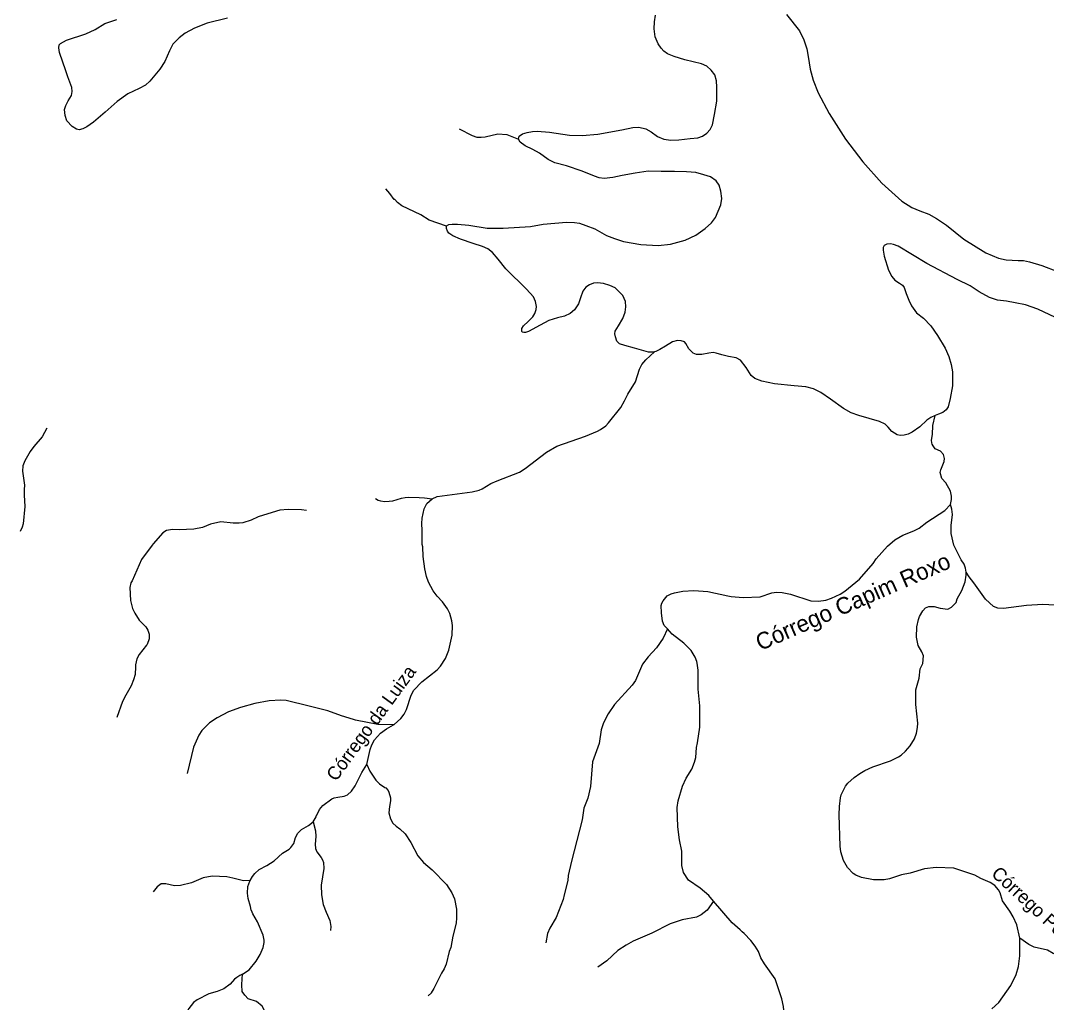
# Model space of a CAD drawing. Extents: x 396 to 422.2, y 7649.8 to 7677.6.
# Drawn here: x 409.11 to 415.26, y 7662.43 to 7668.32 of the extents above; entities that cross this region are included whole.
import ezdxf
from ezdxf.enums import TextEntityAlignment as Align

# ---------------------------------------------------------------- set-up
doc = ezdxf.new("R2010")
doc.units = 0
doc.header["$LTSCALE"] = 0.032
doc.layers.add('2', color=7, linetype='Continuous', lineweight=25)
doc.layers.add('7', color=7, linetype='Continuous', lineweight=25)
doc.layers.add('61', color=7, linetype='Continuous')

msp = doc.modelspace()

# ---------------------------------------------------------------- linework, layer by layer
at = {"layer": '2'}
for points in [[(409.9784, 7668.0764), (409.947, 7668.0312), (409.888, 7667.9584), (409.8614, 7667.9348), (409.8241, 7667.9151), (409.7552, 7667.8817), (409.6913, 7667.8365), (409.6195, 7667.7716), (409.5497, 7667.7136), (409.5094, 7667.685), (409.4858, 7667.6723), (409.4652, 7667.6664), (409.4484, 7667.6703), (409.4219, 7667.687), (409.3914, 7667.7204), (409.3796, 7667.7529), (409.3767, 7667.7883), (409.3835, 7667.8119), (409.3993, 7667.8404), (409.418, 7667.8719), (409.4219, 7667.8955), (409.4199, 7667.9201), (409.3973, 7667.985), (409.3853, 7668.0195), (409.3472, 7668.1295), (409.3422, 7668.159), (409.3442, 7668.1757), (409.3521, 7668.1846), (409.3885, 7668.2042), (409.5035, 7668.2416), (409.5596, 7668.2681), (409.6186, 7668.3035), (409.6893, 7668.3281)], [(410.3541, 7668.336), (410.2321, 7668.3065), (410.1564, 7668.276)], [(412.0974, 7667.6113), (412.1024, 7667.628), (412.121, 7667.6418), (412.1486, 7667.6516), (412.181, 7667.6565), (412.2095, 7667.6585), (412.2843, 7667.6526), (412.4023, 7667.6349), (412.4799, 7667.6319), (412.5724, 7667.6398), (412.7159, 7667.6664), (412.7828, 7667.6801), (412.8192, 7667.6831), (412.8605, 7667.6723), (412.8929, 7667.6546), (412.9313, 7667.627), (412.9696, 7667.6113), (413.0109, 7667.6054), (413.0581, 7667.6064), (413.126, 7667.6142), (413.1732, 7667.6192), (413.2007, 7667.629), (413.2273, 7667.6457), (413.2469, 7667.6683), (413.2597, 7667.6968), (413.2715, 7667.7578), (413.2862, 7667.8384), (413.2872, 7667.923), (413.2833, 7667.9614), (413.2735, 7667.9958), (413.2518, 7668.0253), (413.2263, 7668.0479), (413.1938, 7668.0626), (413.0935, 7668.0862), (413.0296, 7668.1059), (412.9903, 7668.1226), (412.9677, 7668.1383), (412.9519, 7668.156), (412.9352, 7668.1826), (412.9175, 7668.2249), (412.9106, 7668.2721), (412.9126, 7668.3134), (412.9185, 7668.3547)], [(413.7032, 7668.3576), (413.7808, 7668.2593), (413.8084, 7668.2072), (413.8251, 7668.1521), (413.8339, 7668.1069), (413.8448, 7668.0312), (413.8644, 7667.9653), (413.8939, 7667.8886), (413.9598, 7667.7637), (414.0572, 7667.6113), (414.1604, 7667.4746), (414.2745, 7667.3468), (414.3954, 7667.2396), (414.4554, 7667.2003), (414.5026, 7667.1816), (414.5577, 7667.1619), (414.6029, 7667.1354), (414.6638, 7667.0951), (414.7661, 7667.0105), (414.8989, 7666.9289), (414.9746, 7666.8964), (415.0208, 7666.8876), (415.0916, 7666.8827), (415.125, 7666.8827), (415.1604, 7666.8758), (415.2342, 7666.8532), (415.3286, 7666.8178)], [(410.1564, 7668.276), (410.1004, 7668.2465), (410.064, 7668.219), (410.0266, 7668.1806), (410.006, 7668.1413), (409.9784, 7668.0764)], [(411.6655, 7667.0882), (411.6658, 7667.0902), (411.6805, 7667.099), (411.6992, 7667.101), (411.7317, 7667.102), (411.8005, 7667.0941), (411.9096, 7667.0774), (412.005, 7667.0764), (412.1702, 7667.0872), (412.2459, 7667.101), (412.3846, 7667.1128), (412.4337, 7667.1108), (412.4622, 7667.1069), (412.5006, 7667.0931), (412.5557, 7667.0725), (412.6255, 7667.0321), (412.6727, 7667.0144), (412.7277, 7666.9977), (412.83, 7666.98), (412.9352, 7666.9731), (413.009, 7666.981), (413.0965, 7667.0056), (413.1614, 7667.0351), (413.2164, 7667.0744), (413.2538, 7667.1088), (413.2774, 7667.1413), (413.3108, 7667.217), (413.3157, 7667.2544), (413.3108, 7667.2986), (413.301, 7667.334), (413.2823, 7667.3606), (413.2489, 7667.3842), (413.2086, 7667.3969), (413.1604, 7667.4107), (413.1043, 7667.4146), (413.0335, 7667.4166), (412.9529, 7667.4176), (412.8742, 7667.4186), (412.7966, 7667.4078), (412.7179, 7667.392), (412.6638, 7667.3812), (412.6107, 7667.3753), (412.5802, 7667.3783), (412.5527, 7667.3881), (412.479, 7667.4186), (412.3855, 7667.45), (412.3157, 7667.4687), (412.2754, 7667.4884), (412.2233, 7667.5267), (412.183, 7667.5494), (412.1368, 7667.571), (412.1083, 7667.5936), (412.0974, 7667.6113)], [(412.9118, 7666.3352), (412.9047, 7666.333), (412.8772, 7666.333), (412.7936, 7666.3576), (412.7356, 7666.3733), (412.7022, 7666.3832), (412.6874, 7666.3999), (412.6786, 7666.4245), (412.6746, 7666.4441), (412.6776, 7666.4599), (412.6963, 7666.4913), (412.7238, 7666.5346), (412.7366, 7666.5729), (412.7415, 7666.6054), (412.7395, 7666.6369), (412.7238, 7666.6723), (412.6766, 7666.7185), (412.6442, 7666.7342), (412.6068, 7666.745), (412.5714, 7666.7489), (412.5468, 7666.747), (412.5222, 7666.7381), (412.5016, 7666.7224), (412.4839, 7666.6988), (412.4691, 7666.6595), (412.4563, 7666.6241), (412.4327, 7666.5867), (412.4082, 7666.5651), (412.3737, 7666.5493), (412.3305, 7666.5395), (412.2784, 7666.5238), (412.2282, 7666.4962), (412.1584, 7666.4569), (412.1397, 7666.451), (412.1299, 7666.451), (412.1191, 7666.453), (412.1171, 7666.4589), (412.1171, 7666.4756), (412.1279, 7666.4923), (412.1545, 7666.5169), (412.183, 7666.5454), (412.1958, 7666.5651), (412.2036, 7666.5887), (412.2046, 7666.6064), (412.1987, 7666.6378), (412.1869, 7666.6644), (412.1456, 7666.7106), (412.0217, 7666.8335), (411.9755, 7666.8915), (411.9421, 7666.9309), (411.9145, 7666.9525), (411.8811, 7666.9663), (411.8251, 7666.9859), (411.7494, 7667.0115), (411.7041, 7667.0312), (411.6805, 7667.0469), (411.6727, 7667.0587), (411.6658, 7667.0744), (411.6655, 7667.0882)], [(415.3168, 7666.5415), (415.2096, 7666.5906), (415.1358, 7666.6182), (415.0749, 7666.63), (415.0218, 7666.6388), (414.9687, 7666.6457), (414.9205, 7666.6614), (414.8585, 7666.6949), (414.8054, 7666.7312), (414.7268, 7666.7696), (414.5459, 7666.866), (414.3728, 7666.9692), (414.3453, 7666.98), (414.3276, 7666.983), (414.3049, 7666.982), (414.2892, 7666.9722), (414.2833, 7666.9604), (414.2833, 7666.9446), (414.2902, 7666.9092), (414.3148, 7666.8256), (414.3344, 7666.7873), (414.3531, 7666.7647), (414.3816, 7666.748), (414.3984, 7666.7362), (414.4092, 7666.7204), (414.421, 7666.685), (414.4367, 7666.6447), (414.4534, 7666.6123), (414.4839, 7666.569), (414.5252, 7666.5366), (414.5695, 7666.4913), (414.6088, 7666.4333), (414.655, 7666.3576), (414.6776, 7666.3074), (414.6914, 7666.2593), (414.6992, 7666.216), (414.6983, 7666.1314), (414.6855, 7666.0557), (414.6727, 7666.0066), (414.6609, 7665.9879), (414.6412, 7665.9712), (414.6157, 7665.9613), (414.5946, 7665.9538)], [(414.5946, 7665.9538), (414.5695, 7665.9417), (414.5459, 7665.9259), (414.5026, 7665.8866), (414.4574, 7665.8532), (414.4328, 7665.8423), (414.4082, 7665.8364), (414.3846, 7665.8345), (414.3679, 7665.8384), (414.3354, 7665.8571), (414.3138, 7665.8846), (414.2961, 7665.9013), (414.2607, 7665.9171), (414.1368, 7665.9535), (414.0916, 7665.9692), (414.0454, 7665.9948), (413.9677, 7666.0508), (413.9097, 7666.0911), (413.8654, 7666.1128), (413.8192, 7666.1265), (413.7494, 7666.1314), (413.6314, 7666.1442), (413.5567, 7666.159), (413.5134, 7666.1757), (413.4918, 7666.1934), (413.4623, 7666.2425), (413.4278, 7666.2858), (413.4023, 7666.2996), (413.357, 7666.3074), (413.3167, 7666.3173), (413.2823, 7666.3271), (413.2636, 7666.331), (413.2391, 7666.3271), (413.1968, 7666.3192), (413.1653, 7666.3192), (413.1437, 7666.3271), (413.1191, 7666.3537), (413.1014, 7666.3851), (413.0916, 7666.395), (413.0729, 7666.4009), (413.0512, 7666.4028), (413.0198, 7666.395), (412.9785, 7666.3704), (412.945, 7666.3497), (412.9205, 7666.3379), (412.9118, 7666.3352)]]:
    msp.add_lwpolyline(points, dxfattribs=at)
at = {"layer": '7'}
msp.add_line((413.0195, 7664.6423), (412.9904, 7664.6743), dxfattribs=at)
for points in [[(411.7419, 7667.6727), (411.8192, 7667.6323), (411.8471, 7667.6235), (411.8729, 7667.6218), (411.8985, 7667.6242), (411.9743, 7667.6424), (412.028, 7667.6389), (412.0974, 7667.6113)], [(411.6655, 7667.0882), (411.5626, 7667.1246), (411.5119, 7667.1572), (411.3979, 7667.2118), (411.3724, 7667.2301), (411.3564, 7667.2484), (411.3531, 7667.2488), (411.3271, 7667.2851), (411.3028, 7667.3125)], [(411.5804, 7665.4545), (411.6101, 7665.4685), (411.8195, 7665.4965), (411.861, 7665.5066), (411.8795, 7665.5142), (411.9323, 7665.5461), (411.9694, 7665.563), (412.1029, 7665.6139), (412.1373, 7665.6353), (412.2663, 7665.7345), (412.3276, 7665.7697), (412.4982, 7665.829), (412.5708, 7665.859), (412.5898, 7665.8694), (412.6207, 7665.8926), (412.6369, 7665.9095), (412.71, 7666.0014), (412.7319, 7666.042), (412.753, 7666.0811), (412.7979, 7666.1565), (412.8229, 7666.2321), (412.8362, 7666.2593), (412.8616, 7666.2882), (412.9118, 7666.3352)], [(414.6859, 7665.4207), (414.6925, 7665.4508), (414.6929, 7665.4697), (414.6858, 7665.5009), (414.6584, 7665.5494), (414.634, 7665.5755), (414.6255, 7665.611), (414.628, 7665.6271), (414.6483, 7665.6787), (414.6506, 7665.6958), (414.6449, 7665.7198), (414.6267, 7665.7397), (414.5943, 7665.7547), (414.5819, 7665.7712), (414.5776, 7665.7819), (414.5747, 7665.7891), (414.5726, 7665.8063), (414.578, 7665.8407), (414.5804, 7665.8933), (414.5946, 7665.9538)], [(409.27, 7665.8786), (409.2426, 7665.8256), (409.1917, 7665.7684), (409.1706, 7665.7383), (409.1631, 7665.7248), (409.1391, 7665.6815), (409.1276, 7665.6515), (409.1249, 7665.6209), (409.1359, 7665.537), (409.1352, 7665.5103), (409.1343, 7665.476), (409.1383, 7665.4073), (409.1279, 7665.3051), (409.1232, 7665.2844), (409.1113, 7665.2581)], [(411.2402, 7665.4567), (411.2564, 7665.4468), (411.2699, 7665.4414), (411.2969, 7665.4382), (411.3222, 7665.4392), (411.3447, 7665.4423), (411.396, 7665.4585), (411.4181, 7665.463), (411.441, 7665.4648), (411.5027, 7665.463), (411.5349, 7665.4595), (411.5804, 7665.4545)], [(411.5205, 7665.1804), (411.5205, 7665.2637), (411.5172, 7665.3067), (411.5205, 7665.339), (411.5329, 7665.3947), (411.5487, 7665.4255), (411.5804, 7665.4545)], [(412.9904, 7664.6743), (412.9713, 7664.6953), (412.9597, 7664.7205), (412.9538, 7664.7702), (412.952, 7664.8151), (412.956, 7664.8289), (412.9643, 7664.8434), (412.9892, 7664.873), (413.0131, 7664.8847), (413.0333, 7664.891), (413.0827, 7664.8999), (413.1477, 7664.9039), (413.2332, 7664.8976), (413.352, 7664.8718), (413.3714, 7664.8676), (413.4432, 7664.8625), (413.5458, 7664.8656), (413.6153, 7664.89), (413.6436, 7664.8935), (413.6773, 7664.8927), (413.7276, 7664.8825), (413.8504, 7664.8434), (413.8957, 7664.8409), (413.9389, 7664.8474), (413.9732, 7664.8591), (414.0254, 7664.8832), (414.0544, 7664.9001), (414.141, 7664.9725), (414.223, 7665.0656), (414.2422, 7665.0936), (414.3099, 7665.1693), (414.3538, 7665.2085), (414.4005, 7665.2367), (414.4677, 7665.2627), (414.4996, 7665.2786), (414.5442, 7665.3134), (414.6519, 7665.3838), (414.6859, 7665.4207)], [(414.7816, 7665.0153), (414.7772, 7665.0374), (414.7678, 7665.0621), (414.7501, 7665.0885), (414.7058, 7665.1756), (414.6898, 7665.2457), (414.6903, 7665.295), (414.6994, 7665.3597), (414.6946, 7665.3925), (414.6859, 7665.4207)], [(410.8274, 7665.3833), (410.7961, 7665.3875), (410.7166, 7665.3893), (410.668, 7665.3858), (410.543, 7665.348), (410.5373, 7665.3463), (410.4956, 7665.3261), (410.4459, 7665.3104), (410.4238, 7665.3075), (410.388, 7665.3082), (410.3139, 7665.3154), (410.2515, 7665.3028), (410.2034, 7665.2828), (410.1526, 7665.2724), (410.0645, 7665.2677), (410.024, 7665.2699), (409.9882, 7665.2645), (409.9659, 7665.2506), (409.9083, 7665.1846), (409.9017, 7665.177), (409.8389, 7665.0904), (409.7821, 7664.9625), (409.7739, 7664.9507), (409.7676, 7664.9216), (409.7724, 7664.8454), (409.7849, 7664.797), (409.7977, 7664.7677), (409.8243, 7664.726), (409.863, 7664.6873), (409.8767, 7664.6658), (409.884, 7664.6428), (409.884, 7664.614), (409.8714, 7664.5812), (409.8675, 7664.5762), (409.8244, 7664.5206), (409.8108, 7664.4951), (409.8011, 7664.4585), (409.8026, 7664.4342), (409.8006, 7664.4137), (409.7994, 7664.4007), (409.7903, 7664.3683), (409.776, 7664.3331), (409.7432, 7664.277), (409.725, 7664.239), (409.6895, 7664.1432)], [(411.3483, 7664.0999), (411.3518, 7664.1019), (411.3927, 7664.1377), (411.4122, 7664.1633), (411.4268, 7664.1911), (411.4548, 7664.2772), (411.4699, 7664.3072), (411.5181, 7664.3568), (411.6104, 7664.4293), (411.6299, 7664.4512), (411.661, 7664.4967), (411.679, 7664.5464), (411.6991, 7664.6368), (411.7023, 7664.6946), (411.7023, 7664.6949), (411.6983, 7664.7229), (411.6856, 7664.7657), (411.6717, 7664.7954), (411.643, 7664.8372), (411.6096, 7664.8707), (411.586, 7664.9028), (411.5573, 7664.9539), (411.5457, 7664.9875), (411.5365, 7665.0336), (411.5269, 7665.1086), (411.5236, 7665.1663), (411.5205, 7665.1804)], [(415.1022, 7662.819), (415.0842, 7662.9006), (415.0618, 7662.9484), (415.0428, 7662.9815), (414.9977, 7663.0439), (414.9848, 7663.0912), (414.975, 7663.1091), (414.9521, 7663.136), (414.9245, 7663.1533), (414.868, 7663.1767), (414.8324, 7663.1973), (414.7064, 7663.2396), (414.6012, 7663.2443), (414.5311, 7663.2346), (414.4445, 7663.2101), (414.3938, 7663.1988), (414.3221, 7663.1759), (414.2891, 7663.1693), (414.2244, 7663.1701), (414.1538, 7663.1838), (414.1201, 7663.1975), (414.1029, 7663.2082), (414.0698, 7663.2438), (414.0451, 7663.285), (414.0295, 7663.3365), (414.0254, 7663.3719), (414.019, 7663.5585), (414.0214, 7663.6093), (414.0276, 7663.6608), (414.0323, 7663.6791), (414.058, 7663.7321), (414.072, 7663.7495), (414.1096, 7663.7831), (414.1432, 7663.8079), (414.1729, 7663.8257), (414.2221, 7663.8471), (414.3273, 7663.8838), (414.3742, 7663.9067), (414.3911, 7663.918), (414.4176, 7663.9419), (414.4459, 7663.9738), (414.4703, 7664.0144), (414.4829, 7664.0491), (414.4896, 7664.0821), (414.4912, 7664.1096), (414.48, 7664.2202), (414.4791, 7664.3079), (414.4983, 7664.3785), (414.5048, 7664.434), (414.5207, 7664.4665), (414.5242, 7664.5122), (414.5152, 7664.536), (414.4939, 7664.5751), (414.4831, 7664.6244), (414.4857, 7664.6856), (414.4944, 7664.7297), (414.5006, 7664.7482), (414.5204, 7664.7818), (414.5376, 7664.8002), (414.5566, 7664.809), (414.5892, 7664.809), (414.6251, 7664.7977), (414.6704, 7664.7933), (414.6919, 7664.8055), (414.72, 7664.8331), (414.7271, 7664.8535), (414.755, 7664.9044), (414.7741, 7664.9571), (414.7816, 7664.9972), (414.7816, 7665.0153)], [(415.8045, 7664.4143), (415.784, 7664.4737), (415.7728, 7664.4897), (415.7691, 7664.4906), (415.7091, 7664.5512), (415.6462, 7664.6007), (415.6169, 7664.6193), (415.5709, 7664.6431), (415.456, 7664.7169), (415.4333, 7664.7378), (415.4011, 7664.7779), (415.372, 7664.7987), (415.3567, 7664.8057), (415.312, 7664.8156), (415.2398, 7664.821), (415.142, 7664.8154), (415.0037, 7664.7972), (414.9708, 7664.7986), (414.9436, 7664.8081), (414.896, 7664.8516), (414.8267, 7664.9505), (414.7979, 7664.987), (414.7816, 7665.0153)], [(412.9904, 7664.6743), (412.9649, 7664.6179), (412.9255, 7664.5607), (412.8752, 7664.5065), (412.8415, 7664.462), (412.798, 7664.3657), (412.779, 7664.3373), (412.6736, 7664.2213), (412.6357, 7664.1653), (412.607, 7664.1104), (412.5933, 7664.0688), (412.5805, 7663.987), (412.5412, 7663.8772), (412.5284, 7663.7301), (412.5124, 7663.6587), (412.4899, 7663.6003), (412.4791, 7663.5302), (412.4144, 7663.281), (412.3961, 7663.1946), (412.3928, 7663.1655), (412.3705, 7663.0793), (412.3658, 7663.0513), (412.3237, 7662.9432), (412.2862, 7662.8794), (412.2711, 7662.8475), (412.2622, 7662.7922)], [(413.2663, 7663.0425), (413.2384, 7663.075), (413.1854, 7663.1187), (413.1165, 7663.1676), (413.0864, 7663.2137), (413.0772, 7663.2552), (413.0764, 7663.342), (413.0622, 7663.409), (413.0527, 7663.4868), (413.0493, 7663.6024), (413.0547, 7663.644), (413.0806, 7663.7315), (413.1028, 7663.7785), (413.1364, 7663.8332), (413.1527, 7663.8752), (413.16, 7663.904), (413.165, 7663.9625), (413.1712, 7663.9901), (413.184, 7664.0849), (413.184, 7664.2125), (413.1745, 7664.3123), (413.1744, 7664.4269), (413.1676, 7664.4696), (413.1663, 7664.478), (413.156, 7664.5047), (413.1327, 7664.5452), (413.0886, 7664.5879), (413.0195, 7664.6423)], [(411.3483, 7664.0999), (411.2552, 7664.1015), (411.1198, 7664.1276), (411.1087, 7664.1311), (411.037, 7664.1535), (410.9539, 7664.1839), (410.8426, 7664.2112), (410.7042, 7664.2452), (410.6738, 7664.2468), (410.603, 7664.2428), (410.518, 7664.2262), (410.4304, 7664.2027), (410.3596, 7664.176), (410.2911, 7664.1414), (410.2446, 7664.11), (410.1998, 7664.0642), (410.1818, 7664.0361), (410.1506, 7663.9644), (410.1122, 7663.8067)], [(411.1887, 7663.8606), (411.2081, 7663.9517), (411.2181, 7663.9793), (411.2343, 7664.0086), (411.27, 7664.0498), (411.3065, 7664.076), (411.3483, 7664.0999)], [(410.8674, 7663.5181), (410.8854, 7663.5478), (410.8843, 7663.5529), (410.8889, 7663.5572), (410.9053, 7663.5916), (410.9243, 7663.6161), (410.9788, 7663.6559), (410.9922, 7663.6612), (411.0154, 7663.6652), (411.0518, 7663.6714), (411.0722, 7663.6798), (411.0964, 7663.7016), (411.1187, 7663.7328), (411.1589, 7663.814), (411.1887, 7663.8606)], [(411.1887, 7663.8606), (411.2074, 7663.8219), (411.2427, 7663.767), (411.2638, 7663.7459), (411.2967, 7663.7239), (411.3019, 7663.7204), (411.3155, 7663.7053), (411.321, 7663.6944), (411.3297, 7663.6613), (411.3307, 7663.6437), (411.3242, 7663.6093), (411.3212, 7663.5706), (411.3304, 7663.5353), (411.3443, 7663.5102), (411.3636, 7663.4904), (411.3855, 7663.476), (411.4173, 7663.4456), (411.4522, 7663.3937), (411.4951, 7663.3142), (411.5282, 7663.2733), (411.5797, 7663.229), (411.6654, 7663.1425), (411.6987, 7663.0922), (411.7135, 7663.0558), (411.7262, 7662.9935), (411.7262, 7662.9426), (411.723, 7662.9094), (411.704, 7662.8316), (411.6911, 7662.7642), (411.6816, 7662.7391), (411.6642, 7662.6644), (411.6528, 7662.6359), (411.6366, 7662.6105), (411.5903, 7662.5171), (411.5735, 7662.492), (411.576, 7662.4913), (411.5564, 7662.4732)], [(410.4894, 7663.1651), (410.5026, 7663.1902), (410.5174, 7663.2076), (410.5425, 7663.2316), (410.5893, 7663.2565), (410.6326, 7663.2843), (410.6831, 7663.3297), (410.7235, 7663.3537), (410.7331, 7663.3629), (410.75, 7663.3872), (410.7614, 7663.4233), (410.7758, 7663.4488), (410.7977, 7663.4709), (410.8389, 7663.4957), (410.8674, 7663.5181)], [(410.8674, 7663.5181), (410.8816, 7663.4634), (410.8824, 7663.4295), (410.8785, 7663.3831), (410.8802, 7663.3584), (410.8889, 7663.3381), (410.9145, 7663.3027), (410.9229, 7663.2887), (410.9288, 7663.2732), (410.9303, 7663.2379), (410.9152, 7663.138), (410.9176, 7663.0797), (410.9274, 7663.0219), (410.9445, 7662.9752), (410.9672, 7662.9262), (410.9726, 7662.8906), (410.9703, 7662.8656)], [(410.4894, 7663.1651), (410.4499, 7663.1631), (410.4489, 7663.1634), (410.3856, 7663.1804), (410.3501, 7663.1869), (410.2617, 7663.1925), (410.208, 7663.1817), (410.138, 7663.1523), (410.071, 7663.1352), (410.0352, 7663.1328), (409.9833, 7663.1454), (409.9557, 7663.1455), (409.9325, 7663.1277), (409.9072, 7663.0985)], [(410.4438, 7662.6048), (410.4835, 7662.6295), (410.5249, 7662.6828), (410.5491, 7662.7213), (410.5665, 7662.7639), (410.573, 7662.793), (410.573, 7662.8073), (410.5665, 7662.8379), (410.5333, 7662.9171), (410.5043, 7662.9656), (410.498, 7662.9856), (410.495, 7662.9879), (410.4917, 7663.0096), (410.4765, 7663.0581), (410.4733, 7663.0897), (410.4758, 7663.1296), (410.4866, 7663.1613), (410.4894, 7663.1651)], [(413.2663, 7663.0425), (413.2292, 7662.9873), (413.1931, 7662.959), (413.1646, 7662.9452), (413.0775, 7662.929), (413.0067, 7662.9053), (412.8962, 7662.8508), (412.7845, 7662.8017), (412.7425, 7662.7788), (412.6938, 7662.7467), (412.6272, 7662.6843), (412.574, 7662.6463)], [(413.6336, 7662.2002), (413.6413, 7662.2387), (413.6785, 7662.3114), (413.6897, 7662.3658), (413.6863, 7662.4094), (413.6762, 7662.4561), (413.6356, 7662.5757), (413.5713, 7662.6662), (413.5509, 7662.702), (413.5352, 7662.7394), (413.5156, 7662.7725), (413.49, 7662.8068), (413.4502, 7662.8483), (413.4388, 7662.8584), (413.4271, 7662.8688), (413.3786, 7662.9118), (413.2663, 7663.0425)], [(414.9347, 7662.3957), (414.9762, 7662.4349), (415.0474, 7662.536), (415.0796, 7662.6012), (415.094, 7662.6507), (415.102, 7662.7145), (415.1022, 7662.819)], [(415.5549, 7662.5857), (415.5408, 7662.5866), (415.5225, 7662.5897), (415.4789, 7662.5984), (415.4446, 7662.6105), (415.4253, 7662.623), (415.4118, 7662.6406), (415.3897, 7662.68), (415.3588, 7662.7076), (415.3019, 7662.7269), (415.2679, 7662.7475), (415.188, 7662.7653), (415.1553, 7662.7822), (415.1022, 7662.819)], [(410.4438, 7662.6048), (410.4277, 7662.5953), (410.4093, 7662.5845), (410.3958, 7662.5734), (410.3703, 7662.5447), (410.3309, 7662.5164), (410.292, 7662.5001), (410.241, 7662.4858), (410.1719, 7662.45), (410.1501, 7662.4338), (410.121, 7662.3977), (410.1084, 7662.3726), (410.0719, 7662.2686), (410.0579, 7662.1971), (410.053, 7662.1826)], [(410.7112, 7662.2484), (410.6769, 7662.2594), (410.6478, 7662.282), (410.6052, 7662.3308), (410.5607, 7662.4119), (410.5273, 7662.4402), (410.4779, 7662.4554), (410.4564, 7662.4781), (410.4423, 7662.5007), (410.439, 7662.5409), (410.4416, 7662.5756), (410.4438, 7662.6048)]]:
    msp.add_lwpolyline(points, dxfattribs=at)

# ---------------------------------------------------------------- texts
at = {"layer": '61'}
for s, height, rotation, p in [('Córrego Capim Roxo', 0.1, 23.599, (414.1218, 7664.7924)), ('Córrego da Luiza', 0.08, 53.877, (411.246, 7664.0865)), ('Córrego Pedra Branca', 0.08, 317.313, (415.3196, 7662.836))]:
    msp.add_text(s, height=height, rotation=rotation, dxfattribs=at).set_placement(p, align=Align.CENTER)

doc.saveas('drawing.dxf')
